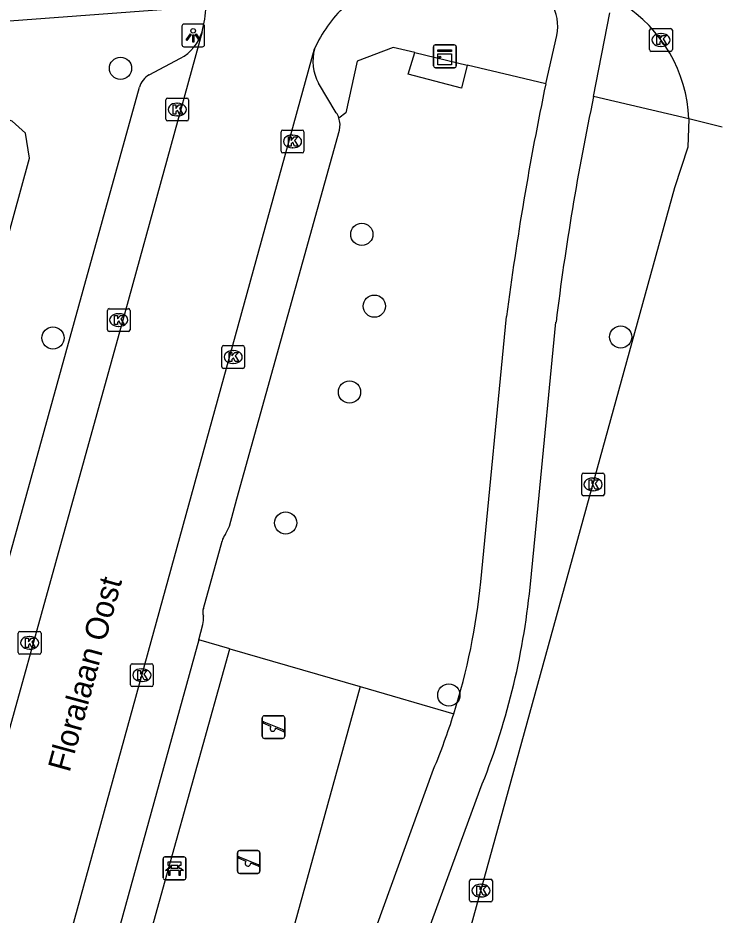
# Model space of a CAD drawing. Extents: x 162542 to 163144, y 380786 to 381511.
# Drawn here: x 163108.1 to 163139.07, y 381099.31 to 381138.75 of the extents above; entities that cross this region are included whole.
import ezdxf

# ---------------------------------------------------------------- set-up
doc = ezdxf.new("R2010")
doc.units = 0
for name, color, linetype in [('IMGEO_Bank', 7, 'Continuous'), ('IMGEO_Berm_groen', 7, 'Continuous'), ('IMGEO_Boom', 7, 'Continuous'), ('IMGEO_Fietspad_gesloten', 7, 'Continuous'), ('IMGEO_Groenvoorziening', 7, 'Continuous'), ('IMGEO_Hek', 7, 'Continuous'), ('IMGEO_Kast', 7, 'Continuous'), ('IMGEO_Kolk', 7, 'Continuous'), ('IMGEO_Lichtpunt', 7, 'Continuous'), ('IMGEO_Openbare_ruimte_label', 7, 'Continuous'), ('IMGEO_Parkeervlak_open', 7, 'Continuous'), ('IMGEO_Rijbaan_lokaal_gesloten', 7, 'Continuous'), ('IMGEO_Rijbaan_lokaal_open', 7, 'Continuous'), ('IMGEO_Speelvoorziening', 7, 'Continuous'), ('IMGEO_Voetpad_open', 7, 'Continuous')]:
    doc.layers.add(name, color=color, linetype=linetype)

msp = doc.modelspace()

# ---------------------------------------------------------------- linework, layer by layer
at = {"layer": 'IMGEO_Bank'}
for p, q in [((163114.485, 381100.938), (163114.485, 381101.779)), ((163114.485, 381101.779), (163114.485, 381100.938)), ((163114.56, 381101.863), (163115.401, 381101.863)), ((163115.401, 381101.863), (163114.56, 381101.863)), ((163115.485, 381101.788), (163115.485, 381100.947)), ((163115.485, 381100.947), (163115.485, 381101.788)), ((163114.794, 381101.369), (163114.794, 381101.475)), ((163114.838, 381101.475), (163114.838, 381101.369)), ((163115.126, 381101.481), (163114.844, 381101.481)), ((163114.844, 381101.363), (163115.126, 381101.363)), ((163115.132, 381101.369), (163115.132, 381101.475)), ((163115.176, 381101.475), (163115.176, 381101.369)), ((163115.182, 381101.261), (163114.789, 381101.261)), ((163115.41, 381100.863), (163114.569, 381100.863)), ((163114.569, 381100.863), (163115.41, 381100.863))]:
    msp.add_line(p, q, dxfattribs=at)
for points in [[(163114.732, 381101.261), (163114.59, 381101.261), (163114.702, 381101.363), (163114.788, 381101.363)], [(163114.788, 381101.481), (163114.702, 381101.481), (163114.702, 381101.642), (163115.265, 381101.642), (163115.265, 381101.481), (163115.182, 381101.481)], [(163115.182, 381101.363), (163115.265, 381101.363), (163115.377, 381101.261), (163115.238, 381101.261)], [(163114.782, 381101.254), (163114.782, 381101.047), (163114.739, 381101.047), (163114.739, 381101.254)], [(163115.232, 381101.254), (163115.232, 381101.047), (163115.188, 381101.047), (163115.188, 381101.254)]]:
    msp.add_lwpolyline(points, dxfattribs=at)
for centre, radius, start, end in [((163114.563, 381101.785), 0.0779, 92.4484, 184.2845), ((163114.563, 381101.785), 0.0779, 92.4484, 184.2845), ((163115.407, 381101.785), 0.0779, 2.4484, 94.2845), ((163115.407, 381101.785), 0.0779, 2.4484, 94.2845), ((163114.787, 381101.474), 0.00671, 2.8957, 87.1043), ((163114.787, 381101.37), 0.00671, 272.8957, 357.1043), ((163114.844, 381101.474), 0.00671, 92.8957, 177.1043), ((163114.844, 381101.37), 0.00671, 182.8957, 267.1043), ((163115.126, 381101.474), 0.00671, 2.8957, 87.1043), ((163115.126, 381101.37), 0.00671, 272.8957, 357.1043), ((163115.183, 381101.474), 0.00671, 92.8957, 177.1043), ((163115.183, 381101.37), 0.00671, 182.8957, 267.1043), ((163114.563, 381100.941), 0.0779, 182.4484, 274.2845), ((163114.563, 381100.941), 0.0779, 182.4484, 274.2845), ((163114.732, 381101.254), 0.00671, 2.8957, 87.1043), ((163114.789, 381101.254), 0.00671, 92.8957, 177.1043), ((163115.181, 381101.254), 0.00671, 2.8957, 87.1043), ((163115.238, 381101.254), 0.00671, 92.8957, 177.1043), ((163115.407, 381100.941), 0.0779, 272.4484, 4.2845), ((163115.407, 381100.941), 0.0779, 272.4484, 4.2845)]:
    msp.add_arc(centre, radius, start, end, dxfattribs=at)
at = {"layer": 'IMGEO_Berm_groen'}
for points in [[(163127.853, 381136.682), (163127.613, 381135.666), (163125.259, 381136.277), (163125.551, 381137.227)], [(163117.414, 381111.017), (163116.047, 381111.414)], [(163117.414, 381111.017), (163123.149, 381109.351)], [(163123.149, 381109.351), (163116.979, 381087.012)], [(163123.149, 381109.351), (163127.267, 381108.155)]]:
    msp.add_lwpolyline(points, dxfattribs=at)
at = {"layer": 'IMGEO_Boom'}
for centre in [(163112.61, 381136.54), (163123.222, 381129.236), (163123.774, 381126.082), (163109.638, 381124.684), (163134.61, 381124.726), (163122.681, 381122.306), (163119.871, 381116.549), (163127.05, 381108.981)]:
    msp.add_circle(centre, 0.489, dxfattribs=at)
at = {"layer": 'IMGEO_Fietspad_gesloten'}
for points in [[(163133.418, 381135.306), (163134.126, 381138.983)], [(163131.317, 381135.862), (163131.799, 381137.979)], [(163128.46, 381113.953), (163129.593, 381125.627)], [(163130.624, 381113.715), (163130.976, 381117.319), (163131.764, 381125.383)], [(163123.86, 381098.765), (163126.379, 381105.719)], [(163125.975, 381098.165), (163128.416, 381104.806)]]:
    msp.add_lwpolyline(points, dxfattribs=at)
for centre, radius, start, end in [((163129.78, 381138.385), 2.059, 348.616, 70.6951), ((163258.715, 381109.14), 130.17, 168.1539, 172.72362), ((163251.975, 381110.445), 121.135, 168.15694, 172.91655), ((163099.435, 381116.903), 29.175, 342.5504, 354.1957), ((163098.588, 381116.927), 32.196, 337.8855, 354.2752), ((163100.282, 381116.612), 28.279, 337.344, 342.5991)]:
    msp.add_arc(centre, radius, start, end, dxfattribs=at)
at = {"layer": 'IMGEO_Groenvoorziening'}
msp.add_lwpolyline([(163111.735, 381090.612), (163117.414, 381111.017)], dxfattribs=at)
at = {"layer": 'IMGEO_Hek'}
for points in [[(163111.735, 381090.612), (163117.414, 381111.017), (163123.149, 381109.351)], [(163123.149, 381109.351), (163116.979, 381087.012)]]:
    msp.add_lwpolyline(points, dxfattribs=at)
at = {"layer": 'IMGEO_Kast'}
for p, q in [((163126.376, 381136.641), (163126.376, 381137.482)), ((163126.376, 381137.482), (163126.376, 381136.641)), ((163126.451, 381137.566), (163127.292, 381137.566)), ((163127.292, 381137.566), (163126.451, 381137.566)), ((163127.376, 381137.491), (163127.376, 381136.65)), ((163127.376, 381136.65), (163127.376, 381137.491)), ((163127.301, 381136.566), (163126.46, 381136.566)), ((163126.46, 381136.566), (163127.301, 381136.566))]:
    msp.add_line(p, q, dxfattribs=at)
for points in [[(163126.571, 381137.356), (163127.171, 381137.356), (163127.171, 381137.271), (163126.571, 381137.271), (163126.571, 381137.356)], [(163126.571, 381137.181), (163127.171, 381137.181), (163127.171, 381136.692), (163126.571, 381136.692), (163126.571, 381137.181)]]:
    msp.add_lwpolyline(points, dxfattribs=at)
msp.add_circle((163126.655, 381137.03), 0.0377, dxfattribs=at)
for centre, start, end in [((163126.454, 381137.488), 92.4484, 184.2845), ((163126.454, 381137.488), 92.4484, 184.2845), ((163127.298, 381137.488), 2.4484, 94.2845), ((163127.298, 381137.488), 2.4484, 94.2845), ((163126.454, 381136.644), 182.4484, 274.2845), ((163126.454, 381136.644), 182.4484, 274.2845), ((163127.298, 381136.644), 272.4484, 4.2845), ((163127.298, 381136.644), 272.4484, 4.2845)]:
    msp.add_arc(centre, 0.0779, start, end, dxfattribs=at)
at = {"layer": 'IMGEO_Kolk'}
for p, q in [((163135.881, 381137.358), (163135.881, 381138.21)), ((163135.956, 381138.284), (163136.808, 381138.284)), ((163136.369, 381138.064), (163136.394, 381138.064)), ((163136.882, 381138.21), (163136.882, 381137.358)), ((163136.808, 381137.284), (163135.956, 381137.284)), ((163136.392, 381137.504), (163136.367, 381137.504)), ((163114.604, 381134.3), (163114.604, 381135.152)), ((163114.679, 381135.226), (163115.531, 381135.226)), ((163115.092, 381135.006), (163115.117, 381135.006)), ((163115.605, 381135.152), (163115.605, 381134.3)), ((163115.531, 381134.226), (163114.679, 381134.226)), ((163115.115, 381134.446), (163115.09, 381134.446)), ((163119.674, 381132.895), (163119.674, 381133.747)), ((163119.749, 381133.821), (163120.601, 381133.821)), ((163120.675, 381133.747), (163120.675, 381132.895)), ((163120.162, 381133.601), (163120.187, 381133.601)), ((163120.185, 381133.041), (163120.16, 381133.041)), ((163120.601, 381132.821), (163119.749, 381132.821)), ((163112.03, 381125.044), (163112.03, 381125.896)), ((163112.105, 381125.97), (163112.957, 381125.97)), ((163113.031, 381125.896), (163113.031, 381125.044)), ((163112.518, 381125.75), (163112.543, 381125.75)), ((163112.541, 381125.19), (163112.516, 381125.19)), ((163112.957, 381124.97), (163112.105, 381124.97)), ((163117.064, 381123.418), (163117.064, 381124.27)), ((163117.139, 381124.344), (163117.991, 381124.344)), ((163118.065, 381124.27), (163118.065, 381123.418)), ((163117.552, 381124.124), (163117.577, 381124.124)), ((163117.575, 381123.564), (163117.55, 381123.564)), ((163117.991, 381123.344), (163117.139, 381123.344)), ((163132.971, 381118.741), (163133.823, 381118.741)), ((163132.896, 381117.815), (163132.896, 381118.667)), ((163133.384, 381118.521), (163133.409, 381118.521)), ((163133.897, 381118.667), (163133.897, 381117.815)), ((163133.407, 381117.961), (163133.382, 381117.961)), ((163133.823, 381117.741), (163132.971, 381117.741)), ((163108.112, 381110.851), (163108.112, 381111.703)), ((163108.187, 381111.777), (163109.039, 381111.777)), ((163109.113, 381111.703), (163109.113, 381110.851)), ((163108.6, 381111.557), (163108.625, 381111.557)), ((163108.623, 381110.997), (163108.598, 381110.997)), ((163109.039, 381110.777), (163108.187, 381110.777)), ((163113.049, 381109.43), (163113.049, 381110.282)), ((163113.124, 381110.356), (163113.976, 381110.356)), ((163113.537, 381110.136), (163113.562, 381110.136)), ((163114.05, 381110.282), (163114.05, 381109.43)), ((163113.976, 381109.356), (163113.124, 381109.356)), ((163113.56, 381109.576), (163113.535, 381109.576)), ((163127.964, 381099.958), (163127.964, 381100.81)), ((163128.039, 381100.884), (163128.891, 381100.884)), ((163128.452, 381100.664), (163128.477, 381100.664)), ((163128.965, 381100.81), (163128.965, 381099.958)), ((163128.891, 381099.884), (163128.039, 381099.884)), ((163128.475, 381100.104), (163128.45, 381100.104))]:
    msp.add_line(p, q, dxfattribs=at)
for points in [[(163135.881, 381137.358), (163135.881, 381138.21)], [(163135.956, 381138.284), (163136.808, 381138.284)], [(163136.882, 381138.21), (163136.882, 381137.358)], [(163136.202, 381137.984), (163136.325, 381137.984), (163136.325, 381137.833), (163136.455, 381137.984), (163136.619, 381137.984), (163136.473, 381137.833), (163136.626, 381137.584), (163136.474, 381137.584), (163136.389, 381137.748), (163136.325, 381137.681), (163136.325, 381137.584), (163136.202, 381137.584), (163136.202, 381137.984)], [(163136.808, 381137.284), (163135.956, 381137.284)], [(163114.604, 381134.3), (163114.604, 381135.152)], [(163114.679, 381135.226), (163115.531, 381135.226)], [(163114.925, 381134.926), (163115.048, 381134.926), (163115.048, 381134.775), (163115.178, 381134.926), (163115.342, 381134.926), (163115.196, 381134.775), (163115.349, 381134.526), (163115.197, 381134.526), (163115.112, 381134.69), (163115.048, 381134.623), (163115.048, 381134.526), (163114.925, 381134.526), (163114.925, 381134.926)], [(163115.605, 381135.152), (163115.605, 381134.3)], [(163115.531, 381134.226), (163114.679, 381134.226)], [(163119.674, 381132.895), (163119.674, 381133.747)], [(163119.749, 381133.821), (163120.601, 381133.821)], [(163120.675, 381133.747), (163120.675, 381132.895)], [(163119.995, 381133.521), (163120.118, 381133.521), (163120.118, 381133.37), (163120.248, 381133.521), (163120.412, 381133.521), (163120.266, 381133.37), (163120.419, 381133.121), (163120.267, 381133.121), (163120.182, 381133.285), (163120.118, 381133.218), (163120.118, 381133.121), (163119.995, 381133.121), (163119.995, 381133.521)], [(163120.601, 381132.821), (163119.749, 381132.821)], [(163112.03, 381125.044), (163112.03, 381125.896)], [(163112.105, 381125.97), (163112.957, 381125.97)], [(163113.031, 381125.896), (163113.031, 381125.044)], [(163112.351, 381125.67), (163112.474, 381125.67), (163112.474, 381125.519), (163112.604, 381125.67), (163112.768, 381125.67), (163112.622, 381125.519), (163112.775, 381125.27), (163112.623, 381125.27), (163112.538, 381125.434), (163112.474, 381125.367), (163112.474, 381125.27), (163112.351, 381125.27), (163112.351, 381125.67)], [(163112.957, 381124.97), (163112.105, 381124.97)], [(163117.064, 381123.418), (163117.064, 381124.27)], [(163117.139, 381124.344), (163117.991, 381124.344)], [(163118.065, 381124.27), (163118.065, 381123.418)], [(163117.385, 381124.044), (163117.508, 381124.044), (163117.508, 381123.893), (163117.638, 381124.044), (163117.802, 381124.044), (163117.656, 381123.893), (163117.809, 381123.644), (163117.657, 381123.644), (163117.572, 381123.808), (163117.508, 381123.741), (163117.508, 381123.644), (163117.385, 381123.644), (163117.385, 381124.044)], [(163117.991, 381123.344), (163117.139, 381123.344)], [(163132.971, 381118.741), (163133.823, 381118.741)], [(163132.896, 381117.815), (163132.896, 381118.667)], [(163133.217, 381118.441), (163133.34, 381118.441), (163133.34, 381118.29), (163133.47, 381118.441), (163133.634, 381118.441), (163133.488, 381118.29), (163133.641, 381118.041), (163133.489, 381118.041), (163133.404, 381118.205), (163133.34, 381118.138), (163133.34, 381118.041), (163133.217, 381118.041), (163133.217, 381118.441)], [(163133.897, 381118.667), (163133.897, 381117.815)], [(163133.823, 381117.741), (163132.971, 381117.741)], [(163108.112, 381110.851), (163108.112, 381111.703)], [(163108.187, 381111.777), (163109.039, 381111.777)], [(163109.113, 381111.703), (163109.113, 381110.851)], [(163108.433, 381111.477), (163108.556, 381111.477), (163108.556, 381111.326), (163108.686, 381111.477), (163108.85, 381111.477), (163108.704, 381111.326), (163108.857, 381111.077), (163108.705, 381111.077), (163108.62, 381111.241), (163108.556, 381111.174), (163108.556, 381111.077), (163108.433, 381111.077), (163108.433, 381111.477)], [(163109.039, 381110.777), (163108.187, 381110.777)], [(163113.049, 381109.43), (163113.049, 381110.282)], [(163113.124, 381110.356), (163113.976, 381110.356)], [(163113.37, 381110.056), (163113.493, 381110.056), (163113.493, 381109.905), (163113.623, 381110.056), (163113.787, 381110.056), (163113.641, 381109.905), (163113.794, 381109.656), (163113.642, 381109.656), (163113.557, 381109.82), (163113.493, 381109.753), (163113.493, 381109.656), (163113.37, 381109.656), (163113.37, 381110.056)], [(163114.05, 381110.282), (163114.05, 381109.43)], [(163113.976, 381109.356), (163113.124, 381109.356)], [(163127.964, 381099.958), (163127.964, 381100.81)], [(163128.039, 381100.884), (163128.891, 381100.884)], [(163128.285, 381100.584), (163128.408, 381100.584), (163128.408, 381100.433), (163128.538, 381100.584), (163128.702, 381100.584), (163128.556, 381100.433), (163128.709, 381100.184), (163128.557, 381100.184), (163128.472, 381100.348), (163128.408, 381100.281), (163128.408, 381100.184), (163128.285, 381100.184), (163128.285, 381100.584)], [(163128.965, 381100.81), (163128.965, 381099.958)], [(163128.891, 381099.884), (163128.039, 381099.884)]]:
    msp.add_lwpolyline(points, dxfattribs=at)
for centre, start, end in [((163135.958, 381138.208), 91.552, 178.448), ((163135.958, 381138.208), 91.552, 178.448), ((163136.806, 381138.208), 1.552, 88.448), ((163136.806, 381138.208), 1.552, 88.448), ((163135.958, 381137.36), 181.552, 268.448), ((163135.958, 381137.36), 181.552, 268.448), ((163136.806, 381137.36), 271.552, 358.448), ((163136.806, 381137.36), 271.552, 358.448), ((163114.681, 381135.15), 91.552, 178.448), ((163114.681, 381135.15), 91.552, 178.448), ((163115.529, 381135.15), 1.552, 88.448), ((163115.529, 381135.15), 1.552, 88.448), ((163114.681, 381134.302), 181.552, 268.448), ((163114.681, 381134.302), 181.552, 268.448), ((163115.529, 381134.302), 271.552, 358.448), ((163115.529, 381134.302), 271.552, 358.448), ((163119.751, 381133.745), 91.552, 178.448), ((163119.751, 381133.745), 91.552, 178.448), ((163120.599, 381133.745), 1.552, 88.448), ((163120.599, 381133.745), 1.552, 88.448), ((163119.751, 381132.897), 181.552, 268.448), ((163119.751, 381132.897), 181.552, 268.448), ((163120.599, 381132.897), 271.552, 358.448), ((163120.599, 381132.897), 271.552, 358.448), ((163112.107, 381125.894), 91.552, 178.448), ((163112.107, 381125.894), 91.552, 178.448), ((163112.955, 381125.894), 1.552, 88.448), ((163112.955, 381125.894), 1.552, 88.448), ((163112.107, 381125.046), 181.552, 268.448), ((163112.107, 381125.046), 181.552, 268.448), ((163112.955, 381125.046), 271.552, 358.448), ((163112.955, 381125.046), 271.552, 358.448), ((163117.141, 381124.268), 91.552, 178.448), ((163117.141, 381124.268), 91.552, 178.448), ((163117.989, 381124.268), 1.552, 88.448), ((163117.989, 381124.268), 1.552, 88.448), ((163117.141, 381123.42), 181.552, 268.448), ((163117.141, 381123.42), 181.552, 268.448), ((163117.989, 381123.42), 271.552, 358.448), ((163117.989, 381123.42), 271.552, 358.448), ((163132.973, 381118.665), 91.552, 178.448), ((163132.973, 381118.665), 91.552, 178.448), ((163133.821, 381118.665), 1.552, 88.448), ((163133.821, 381118.665), 1.552, 88.448), ((163132.973, 381117.817), 181.552, 268.448), ((163132.973, 381117.817), 181.552, 268.448), ((163133.821, 381117.817), 271.552, 358.448), ((163133.821, 381117.817), 271.552, 358.448), ((163108.189, 381111.701), 91.552, 178.448), ((163108.189, 381111.701), 91.552, 178.448), ((163109.037, 381111.701), 1.552, 88.448), ((163109.037, 381111.701), 1.552, 88.448), ((163108.189, 381110.853), 181.552, 268.448), ((163108.189, 381110.853), 181.552, 268.448), ((163109.037, 381110.853), 271.552, 358.448), ((163109.037, 381110.853), 271.552, 358.448), ((163113.126, 381110.28), 91.552, 178.448), ((163113.126, 381110.28), 91.552, 178.448), ((163113.974, 381110.28), 1.552, 88.448), ((163113.974, 381110.28), 1.552, 88.448), ((163113.126, 381109.432), 181.552, 268.448), ((163113.126, 381109.432), 181.552, 268.448), ((163113.974, 381109.432), 271.552, 358.448), ((163113.974, 381109.432), 271.552, 358.448), ((163128.041, 381100.808), 91.552, 178.448), ((163128.041, 381100.808), 91.552, 178.448), ((163128.889, 381100.808), 1.552, 88.448), ((163128.889, 381100.808), 1.552, 88.448), ((163128.041, 381099.96), 181.552, 268.448), ((163128.041, 381099.96), 181.552, 268.448), ((163128.889, 381099.96), 271.552, 358.448), ((163128.889, 381099.96), 271.552, 358.448)]:
    msp.add_arc(centre, 0.0765, start, end, dxfattribs=at)
for centre, major_axis, ratio, start_param, end_param in [((163136.368, 381137.784), (-0.387, 0.002), 0.722429, 4.712389, 7.853982), ((163136.393, 381137.784), (-0.39, 0.002), 0.717154, 1.570796, 4.712389), ((163115.091, 381134.726), (-0.387, 0.002), 0.722429, 4.712389, 7.853982), ((163115.116, 381134.726), (-0.39, 0.002), 0.717154, 1.570796, 4.712389), ((163120.161, 381133.321), (-0.387, 0.002), 0.722429, 4.712389, 7.853982), ((163120.186, 381133.321), (-0.39, 0.002), 0.717154, 1.570796, 4.712389), ((163112.517, 381125.47), (-0.387, 0.002), 0.722429, 4.712389, 7.853982), ((163112.542, 381125.47), (-0.39, 0.002), 0.717154, 1.570796, 4.712389), ((163117.551, 381123.844), (-0.387, 0.002), 0.722429, 4.712389, 7.853982), ((163117.576, 381123.844), (-0.39, 0.002), 0.717154, 1.570796, 4.712389), ((163133.383, 381118.241), (-0.387, 0.002), 0.722429, 4.712389, 7.853982), ((163133.408, 381118.241), (-0.39, 0.002), 0.717154, 1.570796, 4.712389), ((163108.599, 381111.277), (-0.387, 0.002), 0.722429, 4.712389, 7.853982), ((163108.624, 381111.277), (-0.39, 0.002), 0.717154, 1.570796, 4.712389), ((163113.536, 381109.856), (-0.387, 0.002), 0.722429, 4.712389, 7.853982), ((163113.561, 381109.856), (-0.39, 0.002), 0.717154, 1.570796, 4.712389), ((163128.451, 381100.384), (-0.387, 0.002), 0.722429, 4.712389, 7.853982), ((163128.476, 381100.384), (-0.39, 0.002), 0.717154, 1.570796, 4.712389)]:
    msp.add_ellipse(centre, major_axis=major_axis, ratio=ratio, start_param=start_param, end_param=end_param, dxfattribs=at)
at = {"layer": 'IMGEO_Lichtpunt'}
for p, q in [((163116.209, 381138.484), (163115.401, 381138.484)), ((163116.209, 381138.484), (163115.401, 381138.484)), ((163115.307, 381138.389), (163115.307, 381137.582)), ((163115.307, 381138.389), (163115.307, 381137.582)), ((163116.303, 381137.582), (163116.303, 381138.389)), ((163116.303, 381137.582), (163116.303, 381138.389)), ((163115.401, 381137.488), (163116.209, 381137.488)), ((163115.401, 381137.488), (163116.209, 381137.488))]:
    msp.add_line(p, q, dxfattribs=at)
for points in [[(163115.681, 381138.053), (163115.72, 381138.025), (163115.532, 381137.763), (163115.494, 381137.79), (163115.681, 381138.053)], [(163115.783, 381138.005), (163115.83, 381138.005), (163115.83, 381137.683), (163115.783, 381137.683), (163115.783, 381138.005)], [(163115.893, 381138.025), (163115.931, 381138.052), (163116.118, 381137.79), (163116.079, 381137.762), (163115.893, 381138.025)]]:
    msp.add_lwpolyline(points, dxfattribs=at)
msp.add_circle((163115.806, 381138.187), 0.0994, dxfattribs=at)
for centre, start, end in [((163115.401, 381138.389), 90, 180), ((163115.401, 381138.389), 90, 180), ((163116.209, 381138.389), 0, 90), ((163116.209, 381138.389), 0, 90), ((163115.401, 381137.582), 180, 270), ((163115.401, 381137.582), 180, 270), ((163116.209, 381137.582), 270, 0), ((163116.209, 381137.582), 270, 360)]:
    msp.add_arc(centre, 0.0946, start, end, dxfattribs=at)
at = {"layer": 'IMGEO_Parkeervlak_open'}
for points in [[(163117.409, 381116.41), (163117.726, 381117.614), (163122.239, 381133.822)], [(163116.254, 381112.794), (163117.075, 381115.75)], [(163116.047, 381111.414), (163116.223, 381112.08)], [(163116.047, 381111.414), (163115.864, 381110.721), (163111.152, 381093.682)]]:
    msp.add_lwpolyline(points, dxfattribs=at)
for centre, radius, start, end in [((163121.294, 381134.043), 0.971, 346.8413, 18.56), ((163114.476, 381117.773), 3.234, 328.0445, 335.0802), ((163118.064, 381115.478), 1.026, 145.3788, 164.6277), ((163116.694, 381112.631), 0.469, 159.7333, 202.605), ((163115.39, 381112.353), 0.876, 341.866, 6.4377)]:
    msp.add_arc(centre, radius, start, end, dxfattribs=at)
at = {"layer": 'IMGEO_Rijbaan_lokaal_gesloten'}
for points in [[(163137.61, 381134.315), (163137.557, 381133.07), (163136.979, 381131.279), (163105.941, 381018.863), (163101.737, 381003.421), (163101.031, 381000.829)], [(163139.069, 381133.952), (163137.61, 381134.315)]]:
    msp.add_lwpolyline(points, dxfattribs=at)
msp.add_arc((163131.328, 381134.052), 6.288, 2.3957, 57.8904, dxfattribs=at)
at = {"layer": 'IMGEO_Rijbaan_lokaal_open'}
for points in [[(163116.194, 381138.143), (163112.827, 381125.89), (163104.211, 381094.881)], [(163109.061, 381093.574), (163121.145, 381137.399)]]:
    msp.add_lwpolyline(points, dxfattribs=at)
for centre, radius, start, end in [((163110.444, 381139.64), 5.941, 345.4078, 356.4116), ((163126.798, 381134.807), 6.219, 134.1543, 155.3696)]:
    msp.add_arc(centre, radius, start, end, dxfattribs=at)
at = {"layer": 'IMGEO_Speelvoorziening'}
for p, q in [((163118.942, 381108.074), (163119.732, 381108.074)), ((163119.732, 381108.074), (163118.942, 381108.074)), ((163118.842, 381107.174), (163118.842, 381107.974)), ((163118.842, 381107.974), (163118.842, 381107.174)), ((163119.225, 381107.602), (163118.886, 381107.739)), ((163118.911, 381107.799), (163119.787, 381107.446)), ((163119.832, 381107.974), (163119.832, 381107.174)), ((163119.832, 381107.174), (163119.832, 381107.974)), ((163119.763, 381107.386), (163119.423, 381107.523)), ((163119.732, 381107.074), (163118.942, 381107.074)), ((163118.942, 381107.074), (163119.732, 381107.074)), ((163117.854, 381102.142), (163118.644, 381102.142)), ((163118.644, 381102.142), (163117.854, 381102.142)), ((163117.754, 381101.242), (163117.754, 381102.042)), ((163117.754, 381102.042), (163117.754, 381101.242)), ((163118.137, 381101.67), (163117.798, 381101.807)), ((163117.823, 381101.867), (163118.699, 381101.514)), ((163118.744, 381102.042), (163118.744, 381101.242)), ((163118.744, 381101.242), (163118.744, 381102.042)), ((163118.675, 381101.454), (163118.335, 381101.591)), ((163118.644, 381101.142), (163117.854, 381101.142)), ((163117.854, 381101.142), (163118.644, 381101.142))]:
    msp.add_line(p, q, dxfattribs=at)
for centre, radius, start, end in [((163118.942, 381107.974), 0.1, 90, 180), ((163118.942, 381107.974), 0.1, 90, 180), ((163119.732, 381107.974), 0.1, 0, 90), ((163119.732, 381107.974), 0.1, 360, 90), ((163118.899, 381107.769), 0.0327, 68.078, 248.078), ((163119.304, 381107.512), 0.12, 130.9928, 5.1632), ((163119.775, 381107.416), 0.0327, 248.078, 68.078), ((163118.942, 381107.174), 0.1, 180, 270), ((163118.942, 381107.174), 0.1, 180, 270), ((163119.732, 381107.174), 0.1, 270, 0), ((163119.732, 381107.174), 0.1, 270, 0), ((163117.854, 381102.042), 0.1, 90, 180), ((163117.854, 381102.042), 0.1, 90, 180), ((163118.644, 381102.042), 0.1, 0, 90), ((163118.644, 381102.042), 0.1, 360, 90), ((163117.811, 381101.837), 0.0327, 68.078, 248.078), ((163118.216, 381101.58), 0.12, 130.9928, 5.1632), ((163118.687, 381101.484), 0.0327, 248.078, 68.078), ((163117.854, 381101.242), 0.1, 180, 270), ((163117.854, 381101.242), 0.1, 180, 270), ((163118.644, 381101.242), 0.1, 270, 0), ((163118.644, 381101.242), 0.1, 270, 0)]:
    msp.add_arc(centre, radius, start, end, dxfattribs=at)
at = {"layer": 'IMGEO_Voetpad_open'}
for points in [[(163105.933, 381138.5), (163116.374, 381139.268)], [(163125.551, 381137.227), (163124.607, 381137.45), (163123.02, 381136.855), (163122.518, 381134.575), (163122.214, 381134.352)], [(163125.551, 381137.227), (163127.853, 381136.682)], [(163113.867, 381136.249), (163115.244, 381136.978)], [(163131.317, 381135.862), (163129.779, 381136.226), (163127.853, 381136.682)], [(163102.441, 381096.055), (163110.966, 381126.784), (163113.442, 381135.707)], [(163122.098, 381134.585), (163121.32, 381135.882)], [(163137.61, 381134.315), (163133.418, 381135.306)], [(163079.113, 381025.409), (163089.044, 381062.198), (163093.539, 381078.503), (163098.537, 381095.857), (163108.607, 381132.594), (163108.43, 381133.686), (163107.841, 381134.207), (163105.012, 381135.183)]]:
    msp.add_lwpolyline(points, dxfattribs=at)
for centre, radius, start, end in [((163114.334, 381138.69), 1.939, 297.9965, 343.6124), ((163123.141, 381136.861), 2.067, 164.9013, 208.2598), ((163114.298, 381135.474), 0.887, 119.0502, 164.7475), ((163121.333, 381134.059), 0.928, 18.4079, 34.5253)]:
    msp.add_arc(centre, radius, start, end, dxfattribs=at)

# ---------------------------------------------------------------- texts
at = {"layer": 'IMGEO_Openbare_ruimte_label'}
msp.add_text('Floralaan Oost', height=1, rotation=74.6845, dxfattribs=at).set_placement((163110.364, 381105.549))

doc.saveas('drawing.dxf')
